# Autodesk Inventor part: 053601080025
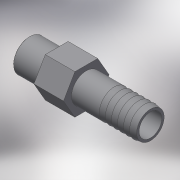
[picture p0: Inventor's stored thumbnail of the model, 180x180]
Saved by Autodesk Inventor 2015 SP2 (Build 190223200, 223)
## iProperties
Created: 2017-10
Part Number: 053601080025
Material: Generic
Description: PLASSON THREADED HOSE NOZZLE 2.1/2"-80
Document SubType Name: Modeling
Designer: KIM
Density: 1 g/cm^3
Appearance: Default
Author: KIM
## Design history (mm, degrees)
derived "053601.ipt"
feature "Solid1::053601.ipt"
tag "TaggingFeature1"
body "Solid1"
other parameters: "d1" = 170 deg, "d6" = 52.6288, "d8" = 33, "d9" = 75.184, "d11" = 29, "d12" = 19, "d13" = 19, "d14" = 0, "d15" = 0.12, "d_" = 12, "R_" = 75.184, "B_" = 19, "Lt_" = 29
